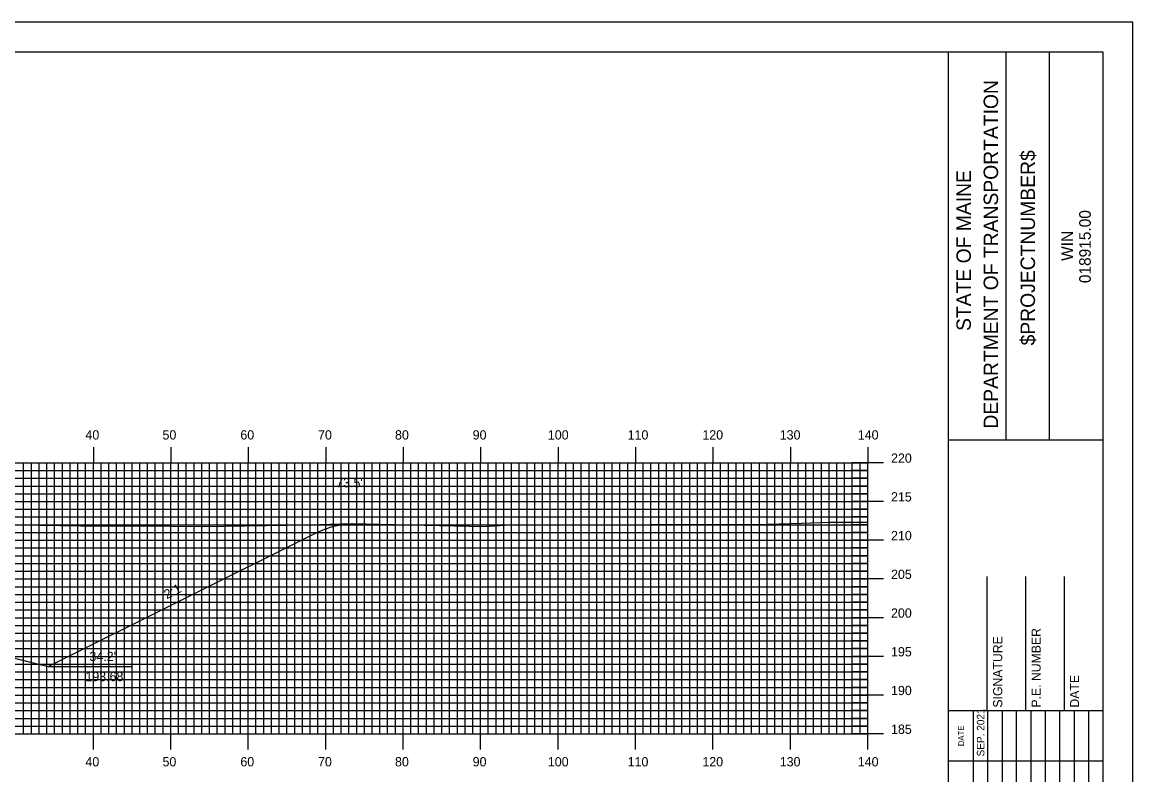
# Model space of a CAD drawing. Extents: x 1799962 to 1800305, y 442591 to 442811.
# Drawn here: x 1800158.3 to 1800301.7, y 442713.4 to 442810.5 of the extents above; entities that cross this region are included whole.
import ezdxf

# ---------------------------------------------------------------- set-up
doc = ezdxf.new("R2010")
doc.units = 0
for name, color, linetype in [('ANNOTATION', 7, 'Continuous'), ('BORDER', 7, 'Continuous'), ('D_Roadway_Centerline', 7, 'Continuous'), ('D_Roadway_SlopeLines', 7, 'Continuous'), ('D_Text_Standard', 7, 'Continuous'), ('H_V ANNOTATION', 7, 'Continuous'), ('MAJOR', 7, 'Continuous'), ('MINOR', 7, 'Continuous'), ('PDRAIN', 7, 'Continuous'), ('PLOT BOUNDARY', 7, 'Continuous'), ('S_Roadway_Centerline', 7, 'Continuous')]:
    doc.layers.add(name, color=color, linetype=linetype)

msp = doc.modelspace()

# ---------------------------------------------------------------- linework, layer by layer
at = {"layer": 'BORDER'}
for p, q in [((1800277.92, 442596.67), (1800277.92, 442806.67)), ((1800285.38, 442756.66), (1800285.38, 442806.66)), ((1800290.97, 442756.66), (1800290.97, 442806.66)), ((1800277.92, 442756.65), (1800297.92, 442756.65)), ((1800282.92, 442721.67), (1800282.92, 442738.97)), ((1800287.92, 442721.67), (1800287.92, 442738.97)), ((1800292.92, 442721.67), (1800292.92, 442738.97)), ((1800277.92, 442721.67), (1800297.92, 442721.67))]:
    msp.add_line(p, q, dxfattribs=at)
msp.add_lwpolyline([(1799977.92, 442596.67), (1800297.92, 442596.67), (1800297.92, 442806.67), (1799977.92, 442806.67)], close=True, dxfattribs=at)
for points in [[(1800281.15, 442715.17), (1800281.15, 442721.67)], [(1800283.02, 442686.68), (1800283.02, 442721.67)], [(1800284.88, 442721.67), (1800284.88, 442686.68)], [(1800286.74, 442686.68), (1800286.74, 442721.67)], [(1800288.61, 442686.68), (1800288.61, 442721.67)], [(1800290.47, 442686.68), (1800290.47, 442721.67)], [(1800292.33, 442686.68), (1800292.33, 442721.67)], [(1800294.2, 442686.68), (1800294.2, 442721.67)], [(1800296.06, 442686.68), (1800296.06, 442721.67)], [(1800281.15, 442686.68), (1800281.15, 442720.26)], [(1800277.92, 442715.17), (1800297.92, 442715.17)]]:
    msp.add_lwpolyline(points, dxfattribs=at)
at = {"layer": 'D_Roadway_Centerline'}
msp.add_lwpolyline([(1800054.16, 442746.18), (1800055.41, 442746.1), (1800056.66, 442745.86), (1800057.91, 442745.47), (1800059.16, 442744.92), (1800093.35, 442727.83), (1800097.35, 442728.83), (1800107.52, 442731.37), (1800115.52, 442731.69), (1800127.52, 442731.45), (1800139.52, 442731.21), (1800147.52, 442730.89), (1800157.7, 442728.35), (1800161.7, 442727.35), (1800196.04, 442744.51), (1800197.29, 442745.07), (1800198.54, 442745.47), (1800199.79, 442745.72), (1800201.04, 442745.83)], dxfattribs=at)
at = {"layer": 'D_Roadway_SlopeLines'}
for points in [[(1800161.7, 442727.35), (1800196.04, 442744.51), (1800197.29, 442745.07), (1800198.54, 442745.47), (1800199.79, 442745.72), (1800201.04, 442745.83)], [(1800147.52, 442730.89), (1800161.7, 442727.35)]]:
    msp.add_lwpolyline(points, dxfattribs=at)
at = {"layer": 'MAJOR'}
for p, q in [((1800167.52, 442755.67), (1800167.52, 442753.67)), ((1800177.52, 442755.67), (1800177.52, 442753.67)), ((1800187.52, 442755.67), (1800187.52, 442753.67)), ((1800197.52, 442755.67), (1800197.52, 442753.67)), ((1800207.52, 442755.67), (1800207.52, 442753.67)), ((1800217.52, 442755.67), (1800217.52, 442753.67)), ((1800227.52, 442755.67), (1800227.52, 442753.67)), ((1800237.52, 442755.67), (1800237.52, 442753.67)), ((1800247.52, 442755.67), (1800247.52, 442753.67)), ((1800257.52, 442755.67), (1800257.52, 442753.67)), ((1800267.52, 442755.67), (1800267.52, 442753.67)), ((1799987.52, 442753.67), (1800267.52, 442753.67)), ((1799987.52, 442753.67), (1800267.52, 442753.67)), ((1800167.52, 442718.67), (1800167.52, 442753.67)), ((1800177.52, 442718.67), (1800177.52, 442753.67)), ((1800187.52, 442718.67), (1800187.52, 442753.67)), ((1800197.52, 442718.67), (1800197.52, 442753.67)), ((1800207.52, 442718.67), (1800207.52, 442753.67)), ((1800217.52, 442718.67), (1800217.52, 442753.67)), ((1800227.52, 442718.67), (1800227.52, 442753.67)), ((1800237.52, 442718.67), (1800237.52, 442753.67)), ((1800247.52, 442718.67), (1800247.52, 442753.67)), ((1800257.52, 442718.67), (1800257.52, 442753.67)), ((1800269.53, 442753.67), (1800265.52, 442753.67)), ((1800267.52, 442718.67), (1800267.52, 442753.67)), ((1800267.52, 442718.67), (1800267.52, 442753.67)), ((1799987.52, 442748.67), (1800267.52, 442748.67)), ((1800269.53, 442748.67), (1800265.52, 442748.67)), ((1799987.52, 442743.67), (1800267.52, 442743.67)), ((1800269.53, 442743.67), (1800265.52, 442743.67)), ((1799987.52, 442738.67), (1800267.52, 442738.67)), ((1800269.53, 442738.67), (1800265.52, 442738.67)), ((1799987.52, 442733.67), (1800267.52, 442733.67)), ((1800269.53, 442733.67), (1800265.52, 442733.67)), ((1799987.52, 442728.67), (1800267.52, 442728.67)), ((1800269.53, 442728.67), (1800265.52, 442728.67)), ((1799987.52, 442723.67), (1800267.52, 442723.67)), ((1800269.53, 442723.67), (1800265.52, 442723.67)), ((1799987.52, 442718.67), (1800267.52, 442718.67)), ((1799987.52, 442718.67), (1800267.52, 442718.67)), ((1800167.52, 442716.66), (1800167.52, 442718.67)), ((1800177.52, 442716.66), (1800177.52, 442718.67)), ((1800187.52, 442716.66), (1800187.52, 442718.67)), ((1800197.52, 442716.66), (1800197.52, 442718.67)), ((1800207.52, 442716.66), (1800207.52, 442718.67)), ((1800217.52, 442716.66), (1800217.52, 442718.67)), ((1800227.52, 442716.66), (1800227.52, 442718.67)), ((1800237.52, 442716.66), (1800237.52, 442718.67)), ((1800247.52, 442716.66), (1800247.52, 442718.67)), ((1800257.52, 442716.66), (1800257.52, 442718.67)), ((1800269.53, 442718.67), (1800265.52, 442718.67)), ((1800267.52, 442716.66), (1800267.52, 442718.67))]:
    msp.add_line(p, q, dxfattribs=at)
at = {"layer": 'MINOR'}
for p, q in [((1799987.52, 442752.67), (1800267.52, 442752.67)), ((1800158.52, 442718.67), (1800158.52, 442753.67)), ((1800159.52, 442718.67), (1800159.52, 442753.67)), ((1800160.52, 442718.67), (1800160.52, 442753.67)), ((1800161.52, 442718.67), (1800161.52, 442753.67)), ((1800162.52, 442718.67), (1800162.52, 442753.67)), ((1800163.52, 442718.67), (1800163.52, 442753.67)), ((1800164.52, 442718.67), (1800164.52, 442753.67)), ((1800165.52, 442718.67), (1800165.52, 442753.67)), ((1800166.52, 442718.67), (1800166.52, 442753.67)), ((1800168.52, 442718.67), (1800168.52, 442753.67)), ((1800169.52, 442718.67), (1800169.52, 442753.67)), ((1800170.52, 442718.67), (1800170.52, 442753.67)), ((1800171.52, 442718.67), (1800171.52, 442753.67)), ((1800172.52, 442718.67), (1800172.52, 442753.67)), ((1800173.52, 442718.67), (1800173.52, 442753.67)), ((1800174.52, 442718.67), (1800174.52, 442753.67)), ((1800175.52, 442718.67), (1800175.52, 442753.67)), ((1800176.52, 442718.67), (1800176.52, 442753.67)), ((1800178.52, 442718.67), (1800178.52, 442753.67)), ((1800179.52, 442718.67), (1800179.52, 442753.67)), ((1800180.52, 442718.67), (1800180.52, 442753.67)), ((1800181.52, 442718.67), (1800181.52, 442753.67)), ((1800182.52, 442718.67), (1800182.52, 442753.67)), ((1800183.52, 442718.67), (1800183.52, 442753.67)), ((1800184.52, 442718.67), (1800184.52, 442753.67)), ((1800185.52, 442718.67), (1800185.52, 442753.67)), ((1800186.52, 442718.67), (1800186.52, 442753.67)), ((1800188.52, 442718.67), (1800188.52, 442753.67)), ((1800189.52, 442718.67), (1800189.52, 442753.67)), ((1800190.52, 442718.67), (1800190.52, 442753.67)), ((1800191.52, 442718.67), (1800191.52, 442753.67)), ((1800192.52, 442718.67), (1800192.52, 442753.67)), ((1800193.52, 442718.67), (1800193.52, 442753.67)), ((1800194.52, 442718.67), (1800194.52, 442753.67)), ((1800195.52, 442718.67), (1800195.52, 442753.67)), ((1800196.52, 442718.67), (1800196.52, 442753.67)), ((1800198.52, 442718.67), (1800198.52, 442753.67)), ((1800199.52, 442718.67), (1800199.52, 442753.67)), ((1800200.52, 442718.67), (1800200.52, 442753.67)), ((1800201.52, 442718.67), (1800201.52, 442753.67)), ((1800202.52, 442718.67), (1800202.52, 442753.67)), ((1800203.52, 442718.67), (1800203.52, 442753.67)), ((1800204.52, 442718.67), (1800204.52, 442753.67)), ((1800205.52, 442718.67), (1800205.52, 442753.67)), ((1800206.52, 442718.67), (1800206.52, 442753.67)), ((1800208.52, 442718.67), (1800208.52, 442753.67)), ((1800209.52, 442718.67), (1800209.52, 442753.67)), ((1800210.52, 442718.67), (1800210.52, 442753.67)), ((1800211.52, 442718.67), (1800211.52, 442753.67)), ((1800212.52, 442718.67), (1800212.52, 442753.67)), ((1800213.52, 442718.67), (1800213.52, 442753.67)), ((1800214.52, 442718.67), (1800214.52, 442753.67)), ((1800215.52, 442718.67), (1800215.52, 442753.67)), ((1800216.52, 442718.67), (1800216.52, 442753.67)), ((1800218.52, 442718.67), (1800218.52, 442753.67)), ((1800219.52, 442718.67), (1800219.52, 442753.67)), ((1800220.52, 442718.67), (1800220.52, 442753.67)), ((1800221.52, 442718.67), (1800221.52, 442753.67)), ((1800222.52, 442718.67), (1800222.52, 442753.67)), ((1800223.52, 442718.67), (1800223.52, 442753.67)), ((1800224.52, 442718.67), (1800224.52, 442753.67)), ((1800225.52, 442718.67), (1800225.52, 442753.67)), ((1800226.52, 442718.67), (1800226.52, 442753.67)), ((1800228.52, 442718.67), (1800228.52, 442753.67)), ((1800229.52, 442718.67), (1800229.52, 442753.67)), ((1800230.52, 442718.67), (1800230.52, 442753.67)), ((1800231.52, 442718.67), (1800231.52, 442753.67)), ((1800232.52, 442718.67), (1800232.52, 442753.67)), ((1800233.52, 442718.67), (1800233.52, 442753.67)), ((1800234.52, 442718.67), (1800234.52, 442753.67)), ((1800235.52, 442718.67), (1800235.52, 442753.67)), ((1800236.52, 442718.67), (1800236.52, 442753.67)), ((1800238.52, 442718.67), (1800238.52, 442753.67)), ((1800239.52, 442718.67), (1800239.52, 442753.67)), ((1800240.52, 442718.67), (1800240.52, 442753.67)), ((1800241.52, 442718.67), (1800241.52, 442753.67)), ((1800242.52, 442718.67), (1800242.52, 442753.67)), ((1800243.52, 442718.67), (1800243.52, 442753.67)), ((1800244.52, 442718.67), (1800244.52, 442753.67)), ((1800245.52, 442718.67), (1800245.52, 442753.67)), ((1800246.52, 442718.67), (1800246.52, 442753.67)), ((1800248.52, 442718.67), (1800248.52, 442753.67)), ((1800249.52, 442718.67), (1800249.52, 442753.67)), ((1800250.52, 442718.67), (1800250.52, 442753.67)), ((1800251.52, 442718.67), (1800251.52, 442753.67)), ((1800252.52, 442718.67), (1800252.52, 442753.67)), ((1800253.52, 442718.67), (1800253.52, 442753.67)), ((1800254.52, 442718.67), (1800254.52, 442753.67)), ((1800255.52, 442718.67), (1800255.52, 442753.67)), ((1800256.52, 442718.67), (1800256.52, 442753.67)), ((1800258.52, 442718.67), (1800258.52, 442753.67)), ((1800259.52, 442718.67), (1800259.52, 442753.67)), ((1800260.52, 442718.67), (1800260.52, 442753.67)), ((1800261.52, 442718.67), (1800261.52, 442753.67)), ((1800262.52, 442718.67), (1800262.52, 442753.67)), ((1800263.52, 442718.67), (1800263.52, 442753.67)), ((1800264.52, 442718.67), (1800264.52, 442753.67)), ((1800265.52, 442718.67), (1800265.52, 442753.67)), ((1800267.52, 442752.67), (1800265.52, 442752.67)), ((1800266.52, 442718.67), (1800266.52, 442753.67)), ((1799987.52, 442751.67), (1800267.52, 442751.67)), ((1800267.52, 442751.67), (1800265.52, 442751.67)), ((1799987.52, 442750.67), (1800267.52, 442750.67)), ((1800267.52, 442750.67), (1800265.52, 442750.67)), ((1799987.52, 442749.67), (1800267.52, 442749.67)), ((1800267.52, 442749.67), (1800265.52, 442749.67)), ((1799987.52, 442747.67), (1800267.52, 442747.67)), ((1800267.52, 442747.67), (1800265.52, 442747.67)), ((1799987.52, 442746.67), (1800267.52, 442746.67)), ((1799987.52, 442745.67), (1800267.52, 442745.67)), ((1800267.52, 442746.67), (1800265.52, 442746.67)), ((1800267.52, 442745.67), (1800265.52, 442745.67)), ((1799987.52, 442744.67), (1800267.52, 442744.67)), ((1800267.52, 442744.67), (1800265.52, 442744.67)), ((1799987.52, 442742.67), (1800267.52, 442742.67)), ((1800267.52, 442742.67), (1800265.52, 442742.67)), ((1799987.52, 442741.67), (1800267.52, 442741.67)), ((1800267.52, 442741.67), (1800265.52, 442741.67)), ((1799987.52, 442740.67), (1800267.52, 442740.67)), ((1800267.52, 442740.67), (1800265.52, 442740.67)), ((1799987.52, 442739.67), (1800267.52, 442739.67)), ((1800267.52, 442739.67), (1800265.52, 442739.67)), ((1799987.52, 442737.67), (1800267.52, 442737.67)), ((1800267.52, 442737.67), (1800265.52, 442737.67)), ((1799987.52, 442736.67), (1800267.52, 442736.67)), ((1799987.52, 442735.67), (1800267.52, 442735.67)), ((1800267.52, 442736.67), (1800265.52, 442736.67)), ((1800267.52, 442735.67), (1800265.52, 442735.67)), ((1799987.52, 442734.67), (1800267.52, 442734.67)), ((1800267.52, 442734.67), (1800265.52, 442734.67)), ((1799987.52, 442732.67), (1800267.52, 442732.67)), ((1800267.52, 442732.67), (1800265.52, 442732.67)), ((1799987.52, 442731.67), (1800267.52, 442731.67)), ((1800267.52, 442731.67), (1800265.52, 442731.67)), ((1799987.52, 442730.67), (1800267.52, 442730.67)), ((1800267.52, 442730.67), (1800265.52, 442730.67)), ((1799987.52, 442729.67), (1800267.52, 442729.67)), ((1800267.52, 442729.67), (1800265.52, 442729.67)), ((1799987.52, 442727.67), (1800267.52, 442727.67)), ((1800267.52, 442727.67), (1800265.52, 442727.67)), ((1799987.52, 442726.67), (1800267.52, 442726.67)), ((1799987.52, 442725.67), (1800267.52, 442725.67)), ((1800267.52, 442726.67), (1800265.52, 442726.67)), ((1800267.52, 442725.67), (1800265.52, 442725.67)), ((1799987.52, 442724.67), (1800267.52, 442724.67)), ((1800267.52, 442724.67), (1800265.52, 442724.67)), ((1799987.52, 442722.67), (1800267.52, 442722.67)), ((1800267.52, 442722.67), (1800265.52, 442722.67)), ((1799987.52, 442721.67), (1800267.52, 442721.67)), ((1800267.52, 442721.67), (1800265.52, 442721.67)), ((1799987.52, 442720.67), (1800267.52, 442720.67)), ((1799987.52, 442719.67), (1800267.52, 442719.67)), ((1800267.52, 442720.67), (1800265.52, 442720.67)), ((1800267.52, 442719.67), (1800265.52, 442719.67))]:
    msp.add_line(p, q, dxfattribs=at)
at = {"layer": 'PDRAIN'}
msp.add_line((1800161.7, 442727.35), (1800172.47, 442727.35), dxfattribs=at)
at = {"layer": 'PLOT BOUNDARY'}
msp.add_lwpolyline([(1799961.74, 442590.55), (1800301.74, 442590.55), (1800301.74, 442810.55), (1799961.74, 442810.55)], close=True, dxfattribs=at)
at = {"layer": 'S_Roadway_Centerline'}
msp.add_lwpolyline([(1800158, 442745.66), (1800165.91, 442745.54), (1800173.65, 442745.54), (1800181.6, 442745.46), (1800195.3, 442745.67), (1800200.9, 442745.83), (1800206.35, 442745.69), (1800218.02, 442745.43), (1800221.98, 442745.7), (1800229.58, 442745.65), (1800239.49, 442745.71), (1800246.52, 442745.7), (1800254.58, 442745.73), (1800258.94, 442745.88), (1800262.53, 442746.01), (1800267.52, 442745.99)], dxfattribs=at)

# ---------------------------------------------------------------- texts
at = {"layer": 'ANNOTATION'}
msp.add_text('2:1', height=1.2, rotation=26.5651, dxfattribs=at).set_placement((1800177.01, 442736.04))
for s, p in [("34.2'", (1800167.01, 442728.07)), ('193.68', (1800166.49, 442725.47))]:
    msp.add_text(s, height=1.2, dxfattribs=at).set_placement(p)
at = {"layer": 'BORDER'}
for s, height, p in [('DEPARTMENT OF TRANSPORTATION', 1.8635, (1800284.34, 442758.08)), ('$PROJECTNUMBER$', 1.8635, (1800289.11, 442768.82)), ('STATE OF MAINE', 1.8635, (1800280.83, 442770.69)), ('018915.00', 1.491, (1800296.31, 442776.86)), ('WIN', 1.491, (1800294, 442779.73)), ('SIGNATURE', 1.181, (1800284.88, 442722.06)), ('P.E. NUMBER', 1.1811, (1800289.84, 442722.06)), ('DATE', 1.181, (1800294.81, 442722.06)), ('SEP. 2021', 0.969, (1800282.57, 442715.76)), ('DATE', 0.743, (1800279.93, 442717.08))]:
    msp.add_text(s, height=height, rotation=90, dxfattribs=at).set_placement(p)
at = {"layer": 'D_Text_Standard'}
msp.add_text("73.5'", height=1.2, dxfattribs=at).set_placement((1800198.88, 442750.49))
at = {"layer": 'H_V ANNOTATION'}
for s, p in [('40', (1800166.5, 442756.67)), ('50', (1800176.45, 442756.67)), ('60', (1800186.5, 442756.67)), ('70', (1800196.53, 442756.67)), ('80', (1800206.47, 442756.67)), ('90', (1800216.5, 442756.67)), ('100', (1800226.21, 442756.67)), ('110', (1800236.51, 442756.67)), ('120', (1800246.16, 442756.67)), ('130', (1800256.15, 442756.67)), ('140', (1800266.23, 442756.67)), ('220', (1800270.52, 442753.67)), ('215', (1800270.52, 442748.67)), ('210', (1800270.52, 442743.67)), ('205', (1800270.52, 442738.67)), ('200', (1800270.52, 442733.67)), ('195', (1800270.52, 442728.67)), ('190', (1800270.52, 442723.67)), ('185', (1800270.52, 442718.67)), ('40', (1800166.5, 442714.47)), ('50', (1800176.45, 442714.47)), ('60', (1800186.5, 442714.47)), ('70', (1800196.53, 442714.47)), ('80', (1800206.47, 442714.47)), ('90', (1800216.5, 442714.47)), ('100', (1800226.21, 442714.47)), ('110', (1800236.51, 442714.47)), ('120', (1800246.16, 442714.47)), ('130', (1800256.15, 442714.47)), ('140', (1800266.23, 442714.47))]:
    msp.add_text(s, height=1.2, dxfattribs=at).set_placement(p)

doc.saveas('drawing.dxf')
